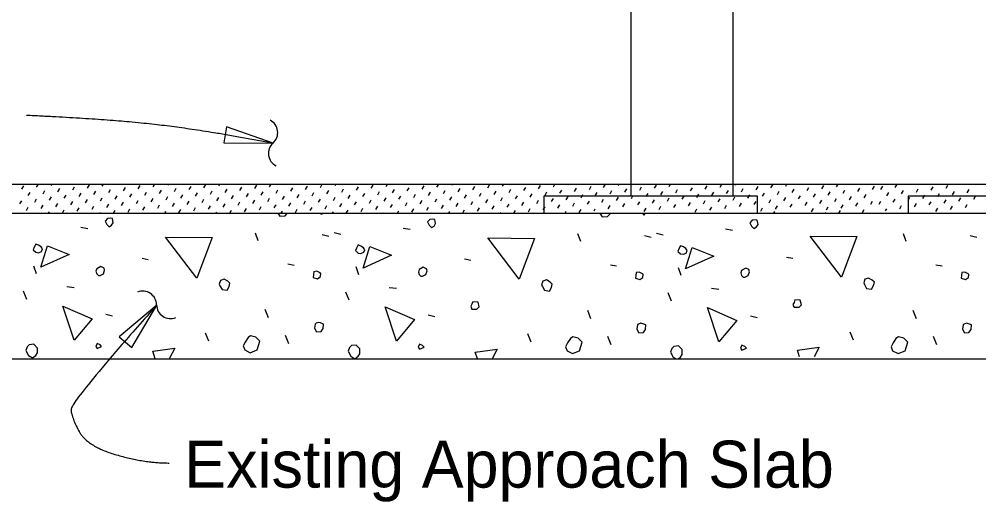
# Model space of a CAD drawing. Extents: x 1.5 to 68.7, y 0 to 31.1.
# Drawn here: x 10.034 to 14.152, y 9.621 to 11.693 of the extents above; entities that cross this region are included whole.
import ezdxf

# ---------------------------------------------------------------- set-up
doc = ezdxf.new("R2010")
doc.units = 0
for name, color, linetype in [('AdhocPoint_dp', 7, 'Continuous'), ('Patterning', 7, 'Continuous'), ('PlotBorder_dp', 7, 'Continuous'), ('SheetBorder_dp', 7, 'Continuous')]:
    doc.layers.add(name, color=color, linetype=linetype)

msp = doc.modelspace()

# ---------------------------------------------------------------- linework, layer by layer
at = {"layer": 'AdhocPoint_dp'}
for points in [[(11.1237, 11.1609), (10.9243, 11.2307), (10.9124, 11.1611)], [(10.6245, 10.4656), (10.4635, 10.3289), (10.5175, 10.2835)]]:
    msp.add_lwpolyline(points, close=True, dxfattribs=at)
for centre, start, end in [((11.0841, 11.2055), 311.5733, 63.3005), ((11.1632, 11.1163), 131.5733, 243.3005), ((10.5642, 10.4655), 0.5042, 112.2314), ((10.6834, 10.4666), 180.5042, 292.2314)]:
    msp.add_arc(centre, 0.0596, start, end, dxfattribs=at)
for points in [[(10.0652, 11.2806), (10.4382, 11.2638), (10.858, 11.2123), (11.1236, 11.1609)], [(10.6244, 10.4656), (10.2576, 10.0524), (10.2576, 9.9848), (10.3251, 9.8601), (10.5693, 9.7873), (10.6784, 9.7873)]]:
    msp.add_open_spline(points, degree=2, dxfattribs=at)
at = {"layer": 'Patterning'}
for p, q in [((12.6601, 10.9324), (12.6601, 11.8211)), ((13.0976, 10.9324), (13.0976, 11.8211)), ((10.0455, 10.9627), (10.0536, 10.9767)), ((10.109, 10.9708), (10.1169, 10.9845)), ((10.1367, 10.9431), (10.1448, 10.9571)), ((10.1725, 10.9789), (10.1757, 10.9845)), ((10.2002, 10.9512), (10.2083, 10.9652)), ((10.2637, 10.9593), (10.2718, 10.9733)), ((10.3272, 10.9674), (10.3353, 10.9814)), ((10.3549, 10.9397), (10.363, 10.9537)), ((10.3907, 10.9755), (10.3959, 10.9845)), ((10.4184, 10.9479), (10.4265, 10.9618)), ((10.4542, 10.9836), (10.4547, 10.9845)), ((10.4819, 10.956), (10.49, 10.9699)), ((10.5454, 10.9641), (10.5535, 10.978)), ((10.6089, 10.9722), (10.616, 10.9845)), ((10.6366, 10.9445), (10.6447, 10.9585)), ((10.6724, 10.9803), (10.6748, 10.9845)), ((10.7, 10.9526), (10.7082, 10.9666)), ((10.7635, 10.9607), (10.7716, 10.9747)), ((10.827, 10.9688), (10.8351, 10.9828)), ((10.8547, 10.9411), (10.8628, 10.9551)), ((10.8905, 10.9769), (10.8949, 10.9845)), ((10.9182, 10.9492), (10.9263, 10.9632)), ((10.9817, 10.9573), (10.9898, 10.9713)), ((11.0452, 10.9654), (11.0533, 10.9794)), ((11.1087, 10.9735), (11.1151, 10.9845)), ((11.1364, 10.9458), (11.1445, 10.9598)), ((11.1722, 10.9816), (11.1739, 10.9845)), ((11.1999, 10.9539), (11.208, 10.9679)), ((11.2634, 10.962), (11.2715, 10.976)), ((11.3269, 10.9701), (11.335, 10.9841)), ((11.3546, 10.9424), (11.3627, 10.9564)), ((11.3904, 10.9782), (11.394, 10.9845)), ((11.4181, 10.9505), (11.4262, 10.9645)), ((11.4815, 10.9586), (11.4897, 10.9726)), ((11.545, 10.9667), (11.5531, 10.9807)), ((11.6085, 10.9748), (11.6141, 10.9845)), ((11.6362, 10.9471), (11.6443, 10.9611)), ((11.672, 10.9829), (11.6729, 10.9845)), ((11.6997, 10.9552), (11.7078, 10.9692)), ((11.7632, 10.9633), (11.7713, 10.9773)), ((11.8267, 10.9714), (11.8343, 10.9845)), ((11.8544, 10.9437), (11.8625, 10.9577)), ((11.8902, 10.9795), (11.8931, 10.9845)), ((11.9179, 10.9518), (11.926, 10.9658)), ((11.9814, 10.9599), (11.9895, 10.9739)), ((12.0449, 10.968), (12.053, 10.982)), ((12.0726, 10.9403), (12.0807, 10.9543)), ((12.1084, 10.9761), (12.1132, 10.9845)), ((12.1361, 10.9484), (12.1442, 10.9624)), ((12.1719, 10.9842), (12.172, 10.9845)), ((12.1996, 10.9565), (12.2077, 10.9705)), ((12.263, 10.9646), (12.2712, 10.9786)), ((12.3265, 10.9727), (12.3333, 10.9845)), ((12.3542, 10.9451), (12.3623, 10.959)), ((12.39, 10.9808), (12.3921, 10.9845)), ((12.4177, 10.9532), (12.4258, 10.9671)), ((12.4812, 10.9613), (12.4893, 10.9753)), ((12.5421, 10.9701), (12.5502, 10.9841)), ((12.5698, 10.9424), (12.5779, 10.9564)), ((12.6056, 10.9782), (12.6093, 10.9845)), ((12.6333, 10.9505), (12.6414, 10.9645)), ((12.6968, 10.9586), (12.7049, 10.9726)), ((12.7603, 10.9667), (12.7684, 10.9807)), ((12.8238, 10.9748), (12.8294, 10.9845)), ((12.8515, 10.9471), (12.8596, 10.9611)), ((12.8873, 10.9829), (12.8882, 10.9845)), ((12.915, 10.9552), (12.9231, 10.9692)), ((12.9785, 10.9633), (12.9866, 10.9773)), ((13.042, 10.9714), (13.0495, 10.9845)), ((13.0697, 10.9437), (13.0778, 10.9577)), ((13.1055, 10.9795), (13.1083, 10.9845)), ((13.1332, 10.9518), (13.1413, 10.9658)), ((13.1966, 10.9599), (13.2047, 10.9739)), ((13.2601, 10.968), (13.2682, 10.982)), ((13.2878, 10.9403), (13.2959, 10.9543)), ((13.3236, 10.9761), (13.3285, 10.9845)), ((13.3513, 10.9484), (13.3594, 10.9624)), ((13.3871, 10.9842), (13.3873, 10.9845)), ((13.4148, 10.9565), (13.4229, 10.9705)), ((13.4783, 10.9646), (13.4864, 10.9786)), ((13.5418, 10.9727), (13.5486, 10.9845)), ((13.5695, 10.9451), (13.5776, 10.959)), ((13.6053, 10.9808), (13.6074, 10.9845)), ((13.633, 10.9532), (13.6411, 10.9671)), ((13.6965, 10.9613), (13.7046, 10.9753)), ((13.7322, 10.9613), (13.7403, 10.9753)), ((13.7931, 10.9701), (13.8013, 10.9841)), ((13.8208, 10.9424), (13.8289, 10.9564)), ((13.8843, 10.9505), (13.8924, 10.9645)), ((13.9478, 10.9586), (13.9559, 10.9726)), ((14.0113, 10.9667), (14.0194, 10.9807)), ((14.1025, 10.9471), (14.1106, 10.9611)), ((10.0374, 10.8992), (10.0455, 10.9132)), ((10.0732, 10.935), (10.0813, 10.949)), ((10.1009, 10.9073), (10.109, 10.9213)), ((10.1644, 10.9154), (10.1725, 10.9294)), ((10.2279, 10.9235), (10.236, 10.9375)), ((10.2914, 10.9316), (10.2995, 10.9456)), ((10.3191, 10.904), (10.3272, 10.9179)), ((10.3826, 10.9121), (10.3907, 10.926)), ((10.4461, 10.9202), (10.4542, 10.9342)), ((10.5096, 10.9283), (10.5177, 10.9423)), ((10.5373, 10.9006), (10.5454, 10.9146)), ((10.5731, 10.9364), (10.5812, 10.9504)), ((10.6008, 10.9087), (10.6089, 10.9227)), ((10.6643, 10.9168), (10.6724, 10.9308)), ((10.7277, 10.9249), (10.7358, 10.9389)), ((10.7912, 10.933), (10.7993, 10.947)), ((10.8189, 10.9053), (10.827, 10.9193)), ((10.8824, 10.9134), (10.8905, 10.9274)), ((10.9459, 10.9215), (10.954, 10.9355)), ((11.0094, 10.9296), (11.0175, 10.9436)), ((11.0371, 10.9019), (11.0452, 10.9159)), ((11.0729, 10.9377), (11.081, 10.9517)), ((11.1006, 10.91), (11.1087, 10.924)), ((11.1641, 10.9181), (11.1722, 10.9321)), ((11.2276, 10.9262), (11.2357, 10.9402)), ((11.2553, 10.8985), (11.2634, 10.9125)), ((11.2911, 10.9343), (11.2992, 10.9483)), ((11.3188, 10.9066), (11.3269, 10.9206)), ((11.3823, 10.9147), (11.3904, 10.9287)), ((11.4458, 10.9228), (11.4539, 10.9368)), ((11.5092, 10.9309), (11.5173, 10.9449)), ((11.5369, 10.9032), (11.545, 10.9172)), ((11.5727, 10.939), (11.5808, 10.953)), ((11.6004, 10.9113), (11.6085, 10.9253)), ((11.6639, 10.9194), (11.672, 10.9334)), ((11.7274, 10.9275), (11.7355, 10.9415)), ((11.7551, 10.8998), (11.7632, 10.9138)), ((11.7909, 10.9356), (11.799, 10.9496)), ((11.8186, 10.9079), (11.8267, 10.9219)), ((11.8821, 10.916), (11.8902, 10.93)), ((11.9456, 10.9241), (11.9537, 10.9381)), ((12.0091, 10.9322), (12.0172, 10.9462)), ((12.0368, 10.9045), (12.0449, 10.9185)), ((12.1003, 10.9126), (12.1084, 10.9266)), ((12.1638, 10.9207), (12.1719, 10.9347)), ((12.2273, 10.9288), (12.2354, 10.9428)), ((12.2549, 10.9012), (12.263, 10.9151)), ((12.2907, 10.9369), (12.2988, 10.9509)), ((12.3184, 10.9093), (12.3265, 10.9232)), ((12.3819, 10.9174), (12.39, 10.9314)), ((12.4454, 10.9255), (12.4535, 10.9395)), ((12.5063, 10.9343), (12.5144, 10.9483)), ((12.534, 10.9066), (12.5421, 10.9206)), ((12.5975, 10.9147), (12.6056, 10.9287)), ((12.661, 10.9228), (12.6691, 10.9368)), ((12.7245, 10.9309), (12.7326, 10.9449)), ((12.7522, 10.9032), (12.7603, 10.9172)), ((12.788, 10.939), (12.7961, 10.953)), ((12.8157, 10.9113), (12.8238, 10.9253)), ((12.8792, 10.9194), (12.8873, 10.9334)), ((12.9427, 10.9275), (12.9508, 10.9415)), ((12.9704, 10.8998), (12.9785, 10.9138)), ((13.0062, 10.9356), (13.0143, 10.9496)), ((13.0339, 10.9079), (13.042, 10.9219)), ((13.0974, 10.916), (13.1055, 10.93)), ((13.1608, 10.9241), (13.169, 10.9381)), ((13.2243, 10.9322), (13.2324, 10.9462)), ((13.252, 10.9045), (13.2601, 10.9185)), ((13.3155, 10.9126), (13.3236, 10.9266)), ((13.379, 10.9207), (13.3871, 10.9347)), ((13.4425, 10.9288), (13.4506, 10.9428)), ((13.4702, 10.9012), (13.4783, 10.9151)), ((13.506, 10.9369), (13.5141, 10.9509)), ((13.5337, 10.9093), (13.5418, 10.9232)), ((13.5972, 10.9174), (13.6053, 10.9314)), ((13.6607, 10.9255), (13.6688, 10.9395)), ((13.7574, 10.9343), (13.7655, 10.9483)), ((13.785, 10.9066), (13.7931, 10.9206)), ((13.8485, 10.9147), (13.8566, 10.9287)), ((13.912, 10.9228), (13.9201, 10.9368)), ((13.9755, 10.9309), (13.9836, 10.9449)), ((14.0032, 10.9032), (14.0113, 10.9172)), ((14.039, 10.939), (14.0471, 10.953)), ((14.0667, 10.9113), (14.0748, 10.9253)), ((14.1302, 10.9194), (14.1383, 10.9334)), ((10.0651, 10.8715), (10.0732, 10.8855)), ((10.1286, 10.8796), (10.1367, 10.8936)), ((10.1921, 10.8877), (10.2002, 10.9017)), ((10.2198, 10.8601), (10.2279, 10.874)), ((10.2556, 10.8958), (10.2637, 10.9098)), ((10.2833, 10.8682), (10.2914, 10.8821)), ((10.3468, 10.8763), (10.3549, 10.8903)), ((10.4103, 10.8844), (10.4184, 10.8984)), ((10.4738, 10.8925), (10.4819, 10.9065)), ((10.5015, 10.8648), (10.5096, 10.8788)), ((10.565, 10.8729), (10.5731, 10.8869)), ((10.6285, 10.881), (10.6366, 10.895)), ((10.6919, 10.8891), (10.7, 10.9031)), ((10.7196, 10.8614), (10.7277, 10.8754)), ((10.7554, 10.8972), (10.7635, 10.9112)), ((10.7831, 10.8695), (10.7912, 10.8835)), ((10.8466, 10.8776), (10.8547, 10.8916)), ((10.9101, 10.8857), (10.9182, 10.8997)), ((10.9387, 10.8595), (10.9459, 10.872)), ((10.9736, 10.8938), (10.9817, 10.9078)), ((11.0013, 10.8661), (11.0094, 10.8801)), ((11.0648, 10.8742), (11.0729, 10.8882)), ((11.1283, 10.8823), (11.1364, 10.8963)), ((11.1918, 10.8904), (11.1999, 10.9044)), ((11.2195, 10.8627), (11.2276, 10.8767)), ((11.283, 10.8708), (11.2911, 10.8848)), ((11.3465, 10.8789), (11.3546, 10.8929)), ((11.41, 10.887), (11.4181, 10.901)), ((11.4377, 10.8595), (11.4458, 10.8733)), ((11.4734, 10.8951), (11.4815, 10.9091)), ((11.5011, 10.8674), (11.5092, 10.8814)), ((11.5646, 10.8755), (11.5727, 10.8895)), ((11.6281, 10.8836), (11.6362, 10.8976)), ((11.6916, 10.8917), (11.6997, 10.9057)), ((11.7193, 10.864), (11.7274, 10.878)), ((11.7828, 10.8721), (11.7909, 10.8861)), ((11.8463, 10.8802), (11.8544, 10.8942)), ((11.9098, 10.8883), (11.9179, 10.9023)), ((11.9375, 10.8606), (11.9456, 10.8746)), ((11.9733, 10.8964), (11.9814, 10.9104)), ((12.001, 10.8687), (12.0091, 10.8827)), ((12.0645, 10.8768), (12.0726, 10.8908)), ((12.128, 10.8849), (12.1361, 10.8989)), ((12.1569, 10.8595), (12.1638, 10.8712)), ((12.1915, 10.893), (12.1996, 10.907)), ((12.2191, 10.8654), (12.2273, 10.8793)), ((12.2826, 10.8735), (12.2907, 10.8875)), ((12.3461, 10.8816), (12.3542, 10.8956)), ((12.4096, 10.8897), (12.4177, 10.9037)), ((12.4373, 10.862), (12.4454, 10.876)), ((12.4731, 10.8978), (12.4812, 10.9118)), ((12.5008, 10.8701), (12.5058, 10.8788)), ((12.5617, 10.8789), (12.5698, 10.8929)), ((12.6252, 10.887), (12.6333, 10.901)), ((12.6887, 10.8951), (12.6968, 10.9091)), ((12.7164, 10.8674), (12.7245, 10.8814)), ((12.7799, 10.8755), (12.788, 10.8895)), ((12.8434, 10.8836), (12.8515, 10.8976)), ((12.9069, 10.8917), (12.915, 10.9057)), ((12.9346, 10.864), (12.9427, 10.878)), ((12.9981, 10.8721), (13.0062, 10.8861)), ((13.0616, 10.8802), (13.0697, 10.8942)), ((13.1251, 10.8883), (13.1332, 10.9023)), ((13.1885, 10.8964), (13.1966, 10.9104)), ((13.2162, 10.8687), (13.2243, 10.8827)), ((13.2797, 10.8768), (13.2878, 10.8908)), ((13.3432, 10.8849), (13.3513, 10.8989)), ((13.4067, 10.893), (13.4148, 10.907)), ((13.4344, 10.8654), (13.4425, 10.8793)), ((13.4979, 10.8735), (13.506, 10.8875)), ((13.552, 10.8595), (13.5588, 10.8712)), ((13.5614, 10.8816), (13.5695, 10.8956)), ((13.6249, 10.8897), (13.633, 10.9037)), ((13.6526, 10.862), (13.6607, 10.876)), ((13.6884, 10.8978), (13.6965, 10.9118)), ((13.7241, 10.8978), (13.7322, 10.9118)), ((13.7518, 10.8701), (13.7569, 10.8788)), ((13.8127, 10.8789), (13.8208, 10.8929)), ((13.8762, 10.887), (13.8843, 10.901)), ((13.9397, 10.8951), (13.9478, 10.9091)), ((13.9674, 10.8674), (13.9755, 10.8814)), ((14.0309, 10.8755), (14.039, 10.8895)), ((14.0944, 10.8836), (14.1025, 10.8976)), ((10.1607, 10.8595), (10.1644, 10.8659)), ((10.3808, 10.8595), (10.3826, 10.8626)), ((10.4396, 10.8595), (10.4461, 10.8707)), ((10.6597, 10.8595), (10.6643, 10.8673)), ((10.8799, 10.8595), (10.8824, 10.8639)), ((11.1, 10.8595), (11.1006, 10.8605)), ((11.1588, 10.8595), (11.1641, 10.8686)), ((11.3789, 10.8595), (11.3823, 10.8652)), ((11.5991, 10.8595), (11.6004, 10.8618)), ((11.6579, 10.8595), (11.6639, 10.8699)), ((11.878, 10.8595), (11.8821, 10.8665)), ((12.0981, 10.8595), (12.1003, 10.8631)), ((12.3183, 10.8595), (12.3184, 10.8598)), ((12.3771, 10.8595), (12.3819, 10.8679)), ((12.9941, 10.8595), (12.9955, 10.8618)), ((13.2731, 10.8595), (13.2772, 10.8665)), ((13.4932, 10.8595), (13.4953, 10.8631)), ((10.2984, 10.7994), (10.3285, 10.7941)), ((11.6817, 10.7958), (11.7117, 10.7905)), ((13.065, 10.7923), (13.095, 10.787)), ((11.0603, 10.741), (11.0479, 10.7746)), ((11.3343, 10.7676), (11.3626, 10.7605)), ((11.386, 10.7768), (11.4143, 10.7698)), ((12.4436, 10.7375), (12.4312, 10.7711)), ((12.7176, 10.764), (12.7459, 10.757)), ((12.7693, 10.7733), (12.7976, 10.7662)), ((13.8407, 10.7375), (13.8283, 10.7711)), ((14.1147, 10.764), (14.143, 10.757)), ((10.5618, 10.6668), (10.5883, 10.6615)), ((13.3274, 10.6715), (13.354, 10.6662)), ((10.1088, 10.5992), (10.0964, 10.6328)), ((11.1876, 10.6421), (11.2141, 10.6368)), ((11.4921, 10.5957), (11.4797, 10.6292)), ((11.9451, 10.6633), (11.9716, 10.658)), ((12.5709, 10.6385), (12.5974, 10.6332)), ((12.8754, 10.5921), (12.863, 10.6257)), ((13.968, 10.6385), (13.9945, 10.6332)), ((10.2383, 10.5448), (10.2701, 10.5413)), ((10.0664, 10.4896), (10.0522, 10.5249)), ((11.4497, 10.486), (11.4355, 10.5214)), ((11.6216, 10.5413), (11.6534, 10.5378)), ((12.8329, 10.4825), (12.8188, 10.5179)), ((13.0049, 10.5378), (13.0367, 10.5342)), ((10.4062, 10.4264), (10.4345, 10.4193)), ((11.1045, 10.4105), (11.0904, 10.4458)), ((11.7895, 10.4229), (11.8178, 10.4158)), ((12.4878, 10.4069), (12.4736, 10.4423)), ((13.1728, 10.4193), (13.2011, 10.4122)), ((13.8849, 10.4069), (13.8707, 10.4423)), ((10.8482, 10.3097), (10.834, 10.3451)), ((12.2315, 10.3062), (12.2173, 10.3415)), ((13.6138, 10.3144), (13.5997, 10.3497)), ((11.1916, 10.2987), (11.1774, 10.334)), ((12.5748, 10.2951), (12.5607, 10.3305)), ((13.9719, 10.2951), (13.9578, 10.3305))]:
    msp.add_line(p, q, dxfattribs=at)
for points in [[(12.2853, 10.8595), (13.2019, 10.8595), (13.2019, 10.9324), (12.2853, 10.9324)], [(13.8495, 10.8595), (14.7661, 10.8595), (14.7661, 10.9324), (13.8495, 10.9324)]]:
    msp.add_lwpolyline(points, close=True, dxfattribs=at)
for points in [[(10.4098, 10.8118), (10.4204, 10.8012), (10.431, 10.8082), (10.4381, 10.8188), (10.4345, 10.8365), (10.4257, 10.8383), (10.4133, 10.8365), (10.4027, 10.8259), (10.4098, 10.8118)], [(11.1446, 10.8594), (11.1522, 10.8471), (11.1752, 10.8489), (11.1841, 10.8577), (11.1857, 10.8594)], [(11.3312, 10.8529), (11.3291, 10.8594)], [(11.3346, 10.8594), (11.3312, 10.8529)], [(11.793, 10.8082), (11.8037, 10.7976), (11.8143, 10.8047), (11.8213, 10.8153), (11.8178, 10.833), (11.809, 10.8347), (11.7966, 10.833), (11.786, 10.8224), (11.793, 10.8082)], [(12.5257, 10.8594), (12.5355, 10.8436), (12.5585, 10.8453), (12.5673, 10.8542), (12.5726, 10.8594)], [(12.7145, 10.8493), (12.7112, 10.8594)], [(12.7197, 10.8594), (12.7145, 10.8493)], [(13.1763, 10.8047), (13.1869, 10.7941), (13.1975, 10.8012), (13.2046, 10.8118), (13.2011, 10.8294), (13.1922, 10.8312), (13.1799, 10.8294), (13.1693, 10.8188), (13.1763, 10.8047)], [(10.7969, 10.5802), (10.6626, 10.757), (10.8623, 10.7552), (10.7969, 10.5802)], [(12.1802, 10.5766), (12.0458, 10.7534), (12.2456, 10.7517), (12.1802, 10.5766)], [(13.5625, 10.5849), (13.4282, 10.7616), (13.628, 10.7599), (13.5625, 10.5849)], [(10.1053, 10.692), (10.1176, 10.6902), (10.13, 10.6955), (10.1336, 10.7061), (10.1283, 10.715), (10.1176, 10.722), (10.1053, 10.7273), (10.0982, 10.7132), (10.0947, 10.7026), (10.1053, 10.692)], [(10.1269, 10.6279), (10.1552, 10.7198), (10.2489, 10.6827), (10.1269, 10.6279)], [(11.4885, 10.6885), (11.5009, 10.6867), (11.5133, 10.692), (11.5168, 10.7026), (11.5115, 10.7114), (11.5009, 10.7185), (11.4885, 10.7238), (11.4815, 10.7097), (11.4779, 10.6991), (11.4885, 10.6885)], [(11.5102, 10.6244), (11.5385, 10.7163), (11.6322, 10.6792), (11.5102, 10.6244)], [(12.8718, 10.6849), (12.8842, 10.6832), (12.8966, 10.6885), (12.9001, 10.6991), (12.8948, 10.7079), (12.8842, 10.715), (12.8718, 10.7203), (12.8648, 10.7061), (12.8612, 10.6955), (12.8718, 10.6849)], [(12.8935, 10.6208), (12.9218, 10.7128), (13.0155, 10.6756), (12.8935, 10.6208)], [(10.3744, 10.5926), (10.3815, 10.5926), (10.3956, 10.5996), (10.4009, 10.6155), (10.3992, 10.6244), (10.385, 10.6314), (10.3673, 10.6208), (10.3638, 10.6102), (10.3673, 10.5996), (10.3744, 10.5926)], [(11.7577, 10.589), (11.7648, 10.589), (11.7789, 10.5961), (11.7842, 10.612), (11.7824, 10.6208), (11.7683, 10.6279), (11.7506, 10.6173), (11.7471, 10.6067), (11.7506, 10.5961), (11.7577, 10.589)], [(13.141, 10.5855), (13.148, 10.5855), (13.1622, 10.5926), (13.1675, 10.6085), (13.1657, 10.6173), (13.1516, 10.6244), (13.1339, 10.6138), (13.1304, 10.6032), (13.1339, 10.5926), (13.141, 10.5855)], [(11.2954, 10.5837), (11.3149, 10.5784), (11.3272, 10.5873), (11.329, 10.5996), (11.3255, 10.6032), (11.3113, 10.6102), (11.299, 10.6085), (11.2972, 10.5961), (11.2954, 10.5837)], [(12.6787, 10.5802), (12.6981, 10.5749), (12.7105, 10.5837), (12.7123, 10.5961), (12.7087, 10.5996), (12.6946, 10.6067), (12.6822, 10.6049), (12.6805, 10.5926), (12.6787, 10.5802)], [(14.0758, 10.5802), (14.0952, 10.5749), (14.1076, 10.5837), (14.1094, 10.5961), (14.1058, 10.5996), (14.0917, 10.6067), (14.0793, 10.6049), (14.0776, 10.5926), (14.0758, 10.5802)], [(10.8959, 10.5484), (10.9047, 10.5325), (10.926, 10.5289), (10.9348, 10.5448), (10.9383, 10.559), (10.9295, 10.5678), (10.9136, 10.5766), (10.8977, 10.5713), (10.8924, 10.5554), (10.8959, 10.5484)], [(12.2792, 10.5448), (12.288, 10.5289), (12.3092, 10.5254), (12.3181, 10.5413), (12.3216, 10.5554), (12.3128, 10.5643), (12.2969, 10.5731), (12.281, 10.5678), (12.2756, 10.5519), (12.2792, 10.5448)], [(13.6615, 10.553), (13.6704, 10.5371), (13.6916, 10.5336), (13.7004, 10.5495), (13.704, 10.5636), (13.6951, 10.5725), (13.6792, 10.5813), (13.6633, 10.576), (13.658, 10.5601), (13.6615, 10.553)], [(10.2697, 10.3146), (10.2219, 10.4613), (10.3475, 10.4065), (10.2697, 10.3146)], [(11.9769, 10.4476), (11.9981, 10.4476), (12.0087, 10.4582), (12.0034, 10.4777), (11.9804, 10.4794), (11.9769, 10.4688), (11.9716, 10.46), (11.9769, 10.4476), (11.9734, 10.4511)], [(13.3593, 10.4558), (13.3805, 10.4558), (13.3911, 10.4664), (13.3858, 10.4859), (13.3628, 10.4876), (13.3593, 10.477), (13.354, 10.4682), (13.3593, 10.4558), (13.3557, 10.4593)], [(11.653, 10.311), (11.6052, 10.4578), (11.7307, 10.403), (11.653, 10.311)], [(13.0362, 10.3075), (12.9885, 10.4542), (13.114, 10.3994), (13.0362, 10.3075)], [(11.3012, 10.3658), (11.31, 10.3499), (11.3294, 10.3517), (11.3383, 10.3641), (11.3401, 10.3835), (11.3277, 10.3888), (11.3188, 10.3906), (11.3082, 10.3871), (11.3047, 10.3835), (11.3012, 10.3658)], [(12.6844, 10.3623), (12.6933, 10.3464), (12.7127, 10.3482), (12.7216, 10.3605), (12.7233, 10.38), (12.711, 10.3853), (12.7021, 10.3871), (12.6915, 10.3835), (12.688, 10.38), (12.6844, 10.3623)], [(14.0815, 10.3623), (14.0904, 10.3464), (14.1098, 10.3482), (14.1187, 10.3605), (14.1204, 10.38), (14.108, 10.3853), (14.0992, 10.3871), (14.0886, 10.3835), (14.0851, 10.38), (14.0815, 10.3623)], [(10.0628, 10.2704), (10.0735, 10.2492), (10.0911, 10.2386), (10.1053, 10.2492), (10.1123, 10.2598), (10.1123, 10.281), (10.0964, 10.2969), (10.077, 10.2951), (10.0681, 10.2863), (10.0628, 10.2704)], [(10.3687, 10.2792), (10.3881, 10.2881), (10.381, 10.2951), (10.3687, 10.3004), (10.3634, 10.2881), (10.3687, 10.2792)], [(11.002, 10.2726), (11.025, 10.2602), (11.055, 10.2726), (11.0674, 10.3097), (11.0497, 10.3274), (11.0267, 10.3327), (11.0161, 10.3256), (11.0037, 10.3062), (10.9949, 10.2903), (11.002, 10.2726)], [(11.7519, 10.2757), (11.7714, 10.2845), (11.7643, 10.2916), (11.7519, 10.2969), (11.7466, 10.2845), (11.7519, 10.2757)], [(12.3852, 10.2691), (12.4082, 10.2567), (12.4383, 10.2691), (12.4507, 10.3062), (12.433, 10.3239), (12.41, 10.3292), (12.3994, 10.3221), (12.387, 10.3026), (12.3782, 10.2867), (12.3852, 10.2691)], [(13.7823, 10.2691), (13.8053, 10.2567), (13.8354, 10.2691), (13.8477, 10.3062), (13.8301, 10.3239), (13.8071, 10.3292), (13.7965, 10.3221), (13.7841, 10.3026), (13.7753, 10.2867), (13.7823, 10.2691)], [(10.6183, 10.2344), (10.6078, 10.2673), (10.7015, 10.2797), (10.6782, 10.2344)], [(11.4461, 10.2668), (11.4567, 10.2456), (11.4744, 10.235), (11.4885, 10.2456), (11.4956, 10.2562), (11.4956, 10.2775), (11.4797, 10.2934), (11.4603, 10.2916), (11.4514, 10.2828), (11.4461, 10.2668)], [(12.0005, 10.2344), (11.991, 10.2638), (12.0847, 10.2761), (12.0633, 10.2344)], [(12.8616, 10.2344), (12.8718, 10.2421), (12.8789, 10.2527), (12.8789, 10.2739), (12.863, 10.2898), (12.8435, 10.2881), (12.8347, 10.2792), (12.8294, 10.2633)], [(12.8294, 10.2633), (12.84, 10.2421), (12.8528, 10.2344)], [(13.1352, 10.2721), (13.1547, 10.281), (13.1476, 10.2881), (13.1352, 10.2934), (13.1299, 10.281), (13.1352, 10.2721)], [(13.3828, 10.2427), (13.3734, 10.272), (13.4671, 10.2843), (13.4456, 10.2427)]]:
    msp.add_lwpolyline(points, dxfattribs=at)
at = {"layer": 'PlotBorder_dp'}
for p, q in [((3.8717, 10.9845), (18.1441, 10.9845)), ((5.8718, 10.8595), (11.8162, 10.8595)), ((11.8162, 10.8595), (18.1441, 10.8595)), ((9.0917, 10.2345), (18.1442, 10.2345))]:
    msp.add_line(p, q, dxfattribs=at)

# ---------------------------------------------------------------- texts
at = {"layer": 'SheetBorder_dp'}
msp.add_text('Existing Approach Slab', height=0.2016, dxfattribs=at).set_placement((10.7426, 9.6816))

doc.saveas('drawing.dxf')
